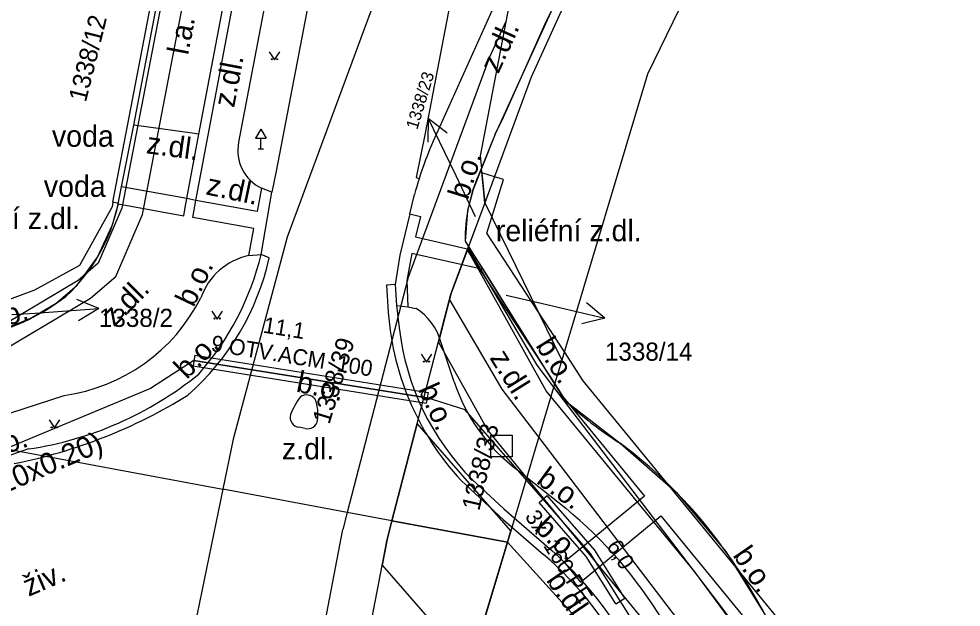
# Model space of a CAD drawing. Extents: x -601602 to -600882, y -1162594 to -1161950.
# Drawn here: x -601319.58 to -601275.41, y -1162307.5 to -1162279.93 of the extents above; entities that cross this region are included whole.
import ezdxf

# ---------------------------------------------------------------- set-up
doc = ezdxf.new("R2010")
doc.units = 0
for name, color, linetype in [('KN_Hranice parcel', 7, 'Continuous'), ('KN_Parcelní čísla', 7, 'Continuous'), ('KN_Pop  PČ popisy', 7, 'Continuous'), ('KN_Vnitřní kresba', 7, 'Continuous'), ('KN_Věcná břemena k části', 7, 'Continuous'), ('VRSTVA 1', 7, 'Continuous'), ('Vrstva 13', 7, 'Continuous'), ('Vrstva 14', 7, 'Continuous'), ('Vrstva 16', 7, 'Continuous'), ('VRSTVA 3', 7, 'Continuous'), ('VRSTVA 5', 7, 'Continuous'), ('Vrstva 6', 7, 'Continuous'), ('Vrstva 8', 7, 'Continuous')]:
    doc.layers.add(name, color=color, linetype=linetype)

# ---------------------------------------------------------------- blocks, each defined once
blk = doc.blocks.new('1029_42')
at = {"layer": 'KN_Pop  PČ popisy'}
for p, q in [((0, 0), (2.924, -0.675)), ((2.924, -0.675), (2.061, 0.038)), ((2.924, -0.675), (1.836, -0.938))]:
    blk.add_line(p, q, dxfattribs=at)
blk = doc.blocks.new('1029_47')
at = {"layer": 'KN_Pop  PČ popisy'}
for p, q in [((-1.316, 2.697), (-1.327, 1.578)), ((0, 0), (-1.316, 2.697)), ((-1.316, 2.697), (-0.426, 2.017))]:
    blk.add_line(p, q, dxfattribs=at)
blk = doc.blocks.new('1029_84')
at = {"layer": 'KN_Pop  PČ popisy'}
for p, q in [((2.994, 0.209), (1.96, 0.639)), ((0, 0), (2.994, 0.209)), ((2.994, 0.209), (2.03, -0.36))]:
    blk.add_line(p, q, dxfattribs=at)
blk = doc.blocks.new('CabR_3')
at = {"layer": 'Vrstva 14'}
blk.add_lwpolyline([(-1, 1), (1, 1), (1, -1), (-1, -1)], close=True, dxfattribs=at)

msp = doc.modelspace()

# ---------------------------------------------------------------- linework, layer by layer
at = {"layer": 'KN_Hranice parcel'}
for p, q in [((-601315.17, -1162288.53), (-601309.39, -1162258.31)), ((-601297.74, -1162288.55), (-601297.9, -1162286.95)), ((-601297.74, -1162288.55), (-601298.5, -1162290.6)), ((-601297.74, -1162288.55), (-601294.13, -1162295.93)), ((-601298.5, -1162290.6), (-601294.47, -1162297.06)), ((-601294.13, -1162295.93), (-601294.47, -1162297.06)), ((-601294.47, -1162297.06), (-601296.68, -1162304.46)), ((-601325.97, -1162299.01), (-601310.02, -1162301.98)), ((-601309.53, -1162299.63), (-601310.02, -1162301.98)), ((-601310.02, -1162301.98), (-601311.33, -1162308.34)), ((-601296.68, -1162304.46), (-601302.09, -1162303.45))]:
    msp.add_line(p, q, dxfattribs=at)
for points in [[(-601292.2, -1162256.23), (-601296.93, -1162266.11), (-601300.03, -1162272.63), (-601303.08, -1162279.58), (-601307.01, -1162290.16), (-601309.53, -1162299.63)], [(-601292.2, -1162256.23), (-601296.76, -1162280.08), (-601297.96, -1162286.36), (-601297.9, -1162286.95)], [(-601290.15, -1162259.19), (-601292, -1162269.8), (-601293.2, -1162275.74), (-601294.16, -1162278.55), (-601297.26, -1162285.34), (-601297.9, -1162286.95)], [(-601284.78, -1162260.22), (-601289.61, -1162269.86), (-601292.03, -1162274.89), (-601295.56, -1162282.66), (-601297.74, -1162288.55)], [(-601279.73, -1162261.19), (-601290.12, -1162282.53), (-601294.13, -1162295.93)], [(-601297.9, -1162286.95), (-601298.29, -1162287.93), (-601298.55, -1162288.92), (-601298.66, -1162290.35), (-601298.5, -1162290.6)], [(-601325.16, -1162296.29), (-601323.67, -1162295.55), (-601322.13, -1162294.94), (-601320.77, -1162294.65), (-601319.05, -1162293.97), (-601317.83, -1162293.26), (-601316.85, -1162292.41), (-601315.89, -1162291.1), (-601315.19, -1162289.58), (-601314.91, -1162288.59), (-601315.17, -1162288.53)], [(-601315.17, -1162288.53), (-601315.21, -1162288.75), (-601316.74, -1162291.49), (-601318.85, -1162292.65), (-601324.73, -1162294.84)], [(-601302.09, -1162303.45), (-601299.33, -1162292.84), (-601298.5, -1162290.6)], [(-601294.47, -1162297.06), (-601294, -1162297.81), (-601291.4, -1162299.81), (-601288.77, -1162302.11), (-601286.44, -1162304.9), (-601284.62, -1162307.84), (-601283.14, -1162310.6), (-601281.69, -1162312.15), (-601279.73, -1162313.35), (-601233.13, -1162322.35), (-601185.37, -1162331.34)], [(-601302.09, -1162303.45), (-601304.19, -1162303.06), (-601310.02, -1162301.98)], [(-600919.037, -1162396.971), (-600927.7, -1162395.33), (-600949.5, -1162391.18), (-600985.92, -1162384.31), (-601061.31, -1162370.08), (-601128.39, -1162357.28), (-601192.59, -1162345.07), (-601263.97, -1162331.56), (-601288.82, -1162326.8), (-601298.71, -1162324.89), (-601298.28, -1162322.82), (-601301.35, -1162321.33), (-601304.05, -1162318.46), (-601304.21, -1162314.16), (-601302.32, -1162304.33), (-601302.09, -1162303.45)], [(-601296.68, -1162304.46), (-601298.54, -1162310.66), (-601297.99, -1162318.35), (-601285.76, -1162320.53), (-601213.14, -1162334.77)]]:
    msp.add_lwpolyline(points, dxfattribs=at)
at = {"layer": 'KN_Pop  PČ popisy'}
for p, q in [((-601298.17, -1162289.21), (-601299.08, -1162287.29)), ((-601296.73, -1162292.88), (-601295.03, -1162293.28)), ((-601319.91, -1162293.79), (-601318.82, -1162293.72))]:
    msp.add_line(p, q, dxfattribs=at)
at = {"layer": 'KN_Vnitřní kresba'}
for p, q in [((-601297.5, -1162281.71), (-601296.76, -1162280.08)), ((-601301.34, -1162292.11), (-601297.5, -1162281.71)), ((-601301.34, -1162292.11), (-601304.19, -1162303.06)), ((-601304.19, -1162303.06), (-601304.4, -1162303.86)), ((-601306.31, -1162313.97), (-601304.4, -1162303.86))]:
    msp.add_line(p, q, dxfattribs=at)
at = {"layer": 'KN_Věcná břemena k části'}
for points in [[(-601325.9, -1162298.77), (-601316.22, -1162293.02), (-601315.03, -1162292), (-601313.79, -1162289.1), (-601307.84, -1162258.18), (-601307.37, -1162255.4), (-601308.71, -1162257.33), (-601308.82, -1162258.01), (-601314.76, -1162288.81), (-601315.86, -1162291.39), (-601316.8, -1162292.2), (-601325.48, -1162297.36)], [(-601279.01, -1162321.85), (-601278.66, -1162319.78), (-601279.07, -1162317.81), (-601287.9, -1162305.85), (-601294.64, -1162297.63), (-601294.86, -1162297.36), (-601298.55, -1162290.75), (-601299.33, -1162292.84), (-601299.91, -1162295.08), (-601297.6, -1162299.22), (-601295.78, -1162301.44), (-601290.5, -1162307.87), (-601282.21, -1162319.13), (-601282.2, -1162319.78), (-601282.43, -1162321.18)], [(-601296.68, -1162304.46), (-601296.52, -1162303.93), (-601300.91, -1162298.89), (-601302.09, -1162303.45)], [(-601298.42, -1162310.27), (-601296.68, -1162304.46), (-601302.09, -1162303.45), (-601302.32, -1162304.33), (-601302.55, -1162305.53)], [(-601285.76, -1162320.53), (-601281.32, -1162321.4), (-601296.68, -1162304.46), (-601298.42, -1162310.27), (-601290.19, -1162319.74)]]:
    msp.add_lwpolyline(points, close=True, dxfattribs=at)
for points in [[(-601276.28, -1162317.43), (-601288.94, -1162302.01), (-601293.13, -1162296.89), (-601294.01, -1162295.54), (-601295.26, -1162293.63), (-601297.64, -1162289.97), (-601297.41, -1162289.23), (-601296.86, -1162287.47), (-601297.29, -1162287.33), (-601297.88, -1162287.15), (-601297.74, -1162288.55), (-601298.56, -1162290.77), (-601294.46, -1162297.04), (-601294.09, -1162297.61), (-601290.25, -1162302.3), (-601294.02, -1162305.4), (-601293.25, -1162306.33), (-601289.48, -1162303.23), (-601277.6, -1162317.73)], [(-601209.38, -1162327.74), (-601275.12, -1162315.35), (-601278.09, -1162316.28), (-601278.9, -1162317.85), (-601279.27, -1162317.66), (-601286.61, -1162307.54), (-601294.51, -1162297.19), (-601295.28, -1162296.17), (-601298.52, -1162290.66), (-601299.33, -1162292.84), (-601299.4, -1162293.1), (-601296.94, -1162297.29), (-601295.21, -1162299.55), (-601288.21, -1162308.74), (-601280.59, -1162319.26), (-601279.52, -1162319.76), (-601279.87, -1162321.69), (-601281.06, -1162328.29), (-601279.1, -1162328.66), (-601277.9, -1162322.07), (-601277.4, -1162319.32), (-601276.69, -1162317.94), (-601275, -1162317.41), (-601209.74, -1162329.7)]]:
    msp.add_lwpolyline(points, dxfattribs=at)
at = {"layer": 'VRSTVA 1'}
for points in [[(-601297.08, -1162300.063), (-601298.66, -1162298.25), (-601300.44, -1162297.69), (-601311.37, -1162295.94), (-601313.41, -1162297.25), (-601324.41, -1162301.83), (-601331.31, -1162306.58)], [(-601275.371, -1162318.188), (-601275.39, -1162318.185), (-601276.28, -1162318.06), (-601281.81, -1162316.83), (-601284.51, -1162316.21), (-601287.04, -1162314.12), (-601288.27, -1162312.16), (-601291.39, -1162307.21), (-601292.79, -1162304.98), (-601295.01, -1162302.44), (-601297.08, -1162300.063)]]:
    msp.add_lwpolyline(points, dxfattribs=at)
at = {"layer": 'Vrstva 13'}
for p, q in [((-601314.19, -1162284.92), (-601311.3, -1162269.78)), ((-601304.24, -1162269.94), (-601307.52, -1162287.07)), ((-601297.53, -1162269.63), (-601300.54, -1162285.29)), ((-601311.29, -1162288.44), (-601308.13, -1162271.77)), ((-601311.14, -1162285.34), (-601308.52, -1162271.6)), ((-601307.94, -1162278.68), (-601309.28, -1162285.72)), ((-601297.19, -1162279.07), (-601300.01, -1162285.33)), ((-601296.87, -1162284.54), (-601294.84, -1162280.03)), ((-601297.26, -1162285.34), (-601296.87, -1162284.54)), ((-601314.77, -1162287.81), (-601314.19, -1162284.92)), ((-601311.57, -1162285.28), (-601314.19, -1162284.92)), ((-601311.71, -1162288.36), (-601311.14, -1162285.34)), ((-601311.14, -1162285.34), (-601311.57, -1162285.28)), ((-601300.54, -1162285.29), (-601300.95, -1162287.37)), ((-601297.26, -1162285.34), (-601298.05, -1162287.3)), ((-601307.52, -1162287.07), (-601307.72, -1162288.06)), ((-601300.95, -1162287.37), (-601300.81, -1162287.41)), ((-601314.92, -1162288.6), (-601314.77, -1162287.81)), ((-601311.71, -1162288.36), (-601314.77, -1162287.81)), ((-601308.2, -1162287.87), (-601308.41, -1162288.96)), ((-601308.22, -1162290.97), (-601307.72, -1162288.06)), ((-601307.72, -1162288.06), (-601308.2, -1162287.87)), ((-601311.78, -1162288.78), (-601311.71, -1162288.36)), ((-601311.29, -1162288.44), (-601311.71, -1162288.36)), ((-601311.42, -1162289.24), (-601311.29, -1162288.44)), ((-601308.41, -1162288.96), (-601311.29, -1162288.44)), ((-601301.26, -1162289.07), (-601301.03, -1162288.16)), ((-601314.92, -1162288.6), (-601311.844, -1162289.163)), ((-601311.844, -1162289.163), (-601311.78, -1162288.78)), ((-601308.56, -1162289.76), (-601311.42, -1162289.24)), ((-601301.26, -1162289.07), (-601301.72, -1162291.01)), ((-601301.26, -1162289.07), (-601300.75, -1162289.2)), ((-601300.75, -1162289.2), (-601300.99, -1162290.15)), ((-601308.8, -1162291.03), (-601308.56, -1162289.76)), ((-601300.99, -1162290.15), (-601298.42, -1162290.74)), ((-601298.66, -1162290.35), (-601298.42, -1162290.74)), ((-601298.42, -1162290.74), (-601297.82, -1162291.68)), ((-601308.8, -1162291.03), (-601308.22, -1162290.97)), ((-601307.84, -1162291.13), (-601308.22, -1162290.97)), ((-601301.72, -1162291.01), (-601301.94, -1162292.39)), ((-601301.16, -1162290.93), (-601301.39, -1162292.19)), ((-601297.82, -1162291.68), (-601301.16, -1162290.93)), ((-601297.82, -1162291.68), (-601294, -1162297.81)), ((-601301.94, -1162292.39), (-601302.35, -1162292.42)), ((-601302.35, -1162292.42), (-601302.28, -1162293.41)), ((-601301.94, -1162292.39), (-601301.88, -1162293.36)), ((-601301.39, -1162292.19), (-601301.34, -1162293.43)), ((-601301.88, -1162293.36), (-601301.34, -1162293.43)), ((-601301.88, -1162293.36), (-601301.75, -1162294.42)), ((-601301.34, -1162293.43), (-601300.96, -1162293.5)), ((-601299.17, -1162296.94), (-601299.8, -1162295.07)), ((-601321.6, -1162298.92), (-601317.46, -1162297.58)), ((-601306.16, -1162299.13), (-601306.46, -1162299.07)), ((-601296.19, -1162301.09), (-601293.94, -1162302.87)), ((-601298.85, -1162301.57), (-601296.86, -1162303.41)), ((-601298.32, -1162301.54), (-601296.84, -1162302.9)), ((-601296.84, -1162302.9), (-601294.59, -1162304.85)), ((-601296.86, -1162303.41), (-601294.99, -1162305.03))]:
    msp.add_line(p, q, dxfattribs=at)
for centre, radius, start, end in [((-601315.797, -1162269.57), 23.422, 333.4761, 350.4407), ((-601283.27, -1162292.962), 18.398, 155.4903, 164.869), ((-601307.382, -1162286.113), 1.938, 168.3057, 245.0374), ((-601291.28, -1162290.24), 7.381, 156.5262, 180.8539), ((-601322.869, -1162286.962), 8.116, 312.556, 348.3531), ((-601319.677, -1162288.461), 12.134, 311.354, 347.2959), ((-601321.071, -1162287.828), 13.23, 318.5833, 346.2622), ((-601308.194, -1162293.987), 3.018, 101.5778, 161.1178), ((-601323.588, -1162284.902), 10.156, 277.9669, 307.6791), ((-601318.614, -1162289.181), 8.478, 277.8236, 333.1502), ((-601289.301, -1162292.755), 12.996, 182.8886, 222.7096), ((-601302.424, -1162295.795), 2.723, 15.4524, 57.4656), ((-601289.789, -1162293.044), 12.04, 186.5618, 224.8823), ((-601321.538, -1162283.789), 16.478, 278.403, 309.0816), ((-601291.135, -1162294.315), 8.453, 198.0912, 233.271), ((-601324.502, -1162276.856), 24.372, 281.1238, 301.7978), ((-601302.699, -1162300.251), 4.513, 144.6503, 156.8936), ((-601306.097, -1162298.055), 0.502, 35.9283, 124.34), ((-601307.535, -1162298.463), 1.975, 351.945, 20.8637), ((-601282.227, -1162285.195), 17.256, 226.9773, 237.8855), ((-601306.388, -1162298.598), 0.477, 165.6463, 261.2845), ((-601306.048, -1162298.67), 0.474, 256.3603, 351.4746), ((-601304.926, -1162317.935), 22.615, 35.5682, 53.2673), ((-601312.679, -1162320.585), 21.486, 107.4716, 135.2188), ((-601306.991, -1162318.724), 20.534, 31.0574, 50.5387), ((-601306.894, -1162318.54), 18.407, 26.281, 48.0522), ((-601306.8, -1162319.678), 25.156, 24.9417, 36.3157), ((-601305.647, -1162317.479), 16.387, 26.4088, 49.4333)]:
    msp.add_arc(centre, radius, start, end, dxfattribs=at)
at = {"layer": 'VRSTVA 3'}
for points in [[(-601307.849, -1162281.477), (-601307.599, -1162281.852), (-601307.349, -1162281.477)], [(-601310.535, -1162293.627), (-601310.285, -1162294.002), (-601310.035, -1162293.627)], [(-601300.72, -1162295.645), (-601300.47, -1162296.02), (-601300.22, -1162295.645)], [(-601318.166, -1162298.731), (-601317.916, -1162299.106), (-601317.666, -1162298.731)]]:
    msp.add_lwpolyline(points, dxfattribs=at)
for centre in [(-601307.724, -1162281.827), (-601307.474, -1162281.827), (-601310.41, -1162293.977), (-601310.16, -1162293.977), (-601300.595, -1162295.995), (-601300.345, -1162295.995), (-601318.041, -1162299.081), (-601317.791, -1162299.081)]:
    msp.add_circle(centre, 0.025, dxfattribs=at)
at = {"layer": 'VRSTVA 5'}
for p, q in [((-601311.33, -1162295.693), (-601311.41, -1162296.187)), ((-601311.37, -1162295.94), (-601300.44, -1162297.69)), ((-601311.33, -1162295.693), (-601300.4, -1162297.443)), ((-601311.41, -1162296.187), (-601300.48, -1162297.937)), ((-601300.4, -1162297.443), (-601300.48, -1162297.937)), ((-601295.198, -1162302.605), (-601294.822, -1162302.275)), ((-601291.602, -1162307.343), (-601291.178, -1162307.077))]:
    msp.add_line(p, q, dxfattribs=at)
for points in [[(-601291.178, -1162307.077), (-601292.589, -1162304.83), (-601294.822, -1162302.275)], [(-601291.602, -1162307.343), (-601292.991, -1162305.13), (-601295.198, -1162302.605)], [(-601291.39, -1162307.21), (-601292.79, -1162304.98), (-601295.01, -1162302.44)]]:
    msp.add_lwpolyline(points, dxfattribs=at)
at = {"layer": 'Vrstva 8'}
for p, q in [((-601308.24, -1162285.097), (-601308.49, -1162285.53)), ((-601308.24, -1162285.097), (-601307.99, -1162285.53)), ((-601308.49, -1162285.53), (-601307.99, -1162285.53)), ((-601308.24, -1162286.03), (-601308.24, -1162285.53)), ((-601308.365, -1162286.03), (-601308.115, -1162286.03))]:
    msp.add_line(p, q, dxfattribs=at)

# ---------------------------------------------------------------- block references
at = {"layer": 'KN_Pop  PČ popisy'}
for name, p in [('1029_47', (-601299.08, -1162287.29)), ('1029_84', (-601318.82, -1162293.72)), ('1029_42', (-601295.03, -1162293.28))]:
    msp.add_blockref(name, p, dxfattribs=at)
at = {"layer": 'Vrstva 14', "xscale": 0.5, "yscale": 0.5}
msp.add_blockref('CabR_3', (-601296.95, -1162299.95), dxfattribs=at)

# ---------------------------------------------------------------- texts
at = {"layer": 'KN_Parcelní čísla'}
for s, height, rotation, p in [('1338/12', 0.85, 76, (-601316.438, -1162283.873)), ('1338/23', 0.5695, 73, (-601300.905, -1162285.155)), ('1338/39', 0.85, 73, (-601305.027, -1162298.968)), ('1338/33', 0.85, 77, (-601298.001, -1162303.021))]:
    msp.add_text(s, height=height, rotation=rotation, dxfattribs=at).set_placement(p)
for s, p in [('1338/2', (-601315.83, -1162294.37)), ('1338/14', (-601292.11, -1162295.953))]:
    msp.add_text(s, height=0.85, dxfattribs=at).set_placement(p)
at = {"layer": 'Vrstva 16'}
for s, rotation, p in [('l.a.', 79.1576, (-601311.646, -1162281.663)), ('z.dl.', 65.5807, (-601297.106, -1162282.547)), ('z.dl.', 79.2232, (-601309.492, -1162284.126)), ('z.dl.', 352.1763, (-601313.641, -1162286.228)), ('b.o.', 72.5701, (-601298.53, -1162288.452)), ('z.dl.', 348.1386, (-601310.854, -1162288.155)), ('b.o.', 64.5747, (-601311.389, -1162293.486)), ('z.dl.', 44.8768, (-601315.12, -1162294.392)), ('b.o.', 16.719, (-601321.185, -1162294.647)), ('b.o.', 301.9122, (-601295.385, -1162295.238)), ('b.o.', 44.8768, (-601311.711, -1162296.859)), ('z.dl.', 301.9284, (-601297.537, -1162295.817)), ('b.o.', 348.0588, (-601306.622, -1162297.392)), ('b.o.', 293.9458, (-601300.879, -1162297.281)), ('b.dl.(0.10x0.20)', 23.3792, (-601324.074, -1162303.841)), ('b.o.', 19.5747, (-601321.175, -1162300.696)), ('z.dl.', 0.0968, (-601307.247, -1162300.58)), ('b.o.', 323.7693, (-601295.37, -1162301.661)), ('b.o.', 316.5045, (-601295.459, -1162303.855)), ('b.o.', 304.3543, (-601286.143, -1162305.071)), ('živ.', 23.3792, (-601319.121, -1162307.02)), ('b.dl.(0.10x0.20)', 304.3543, (-601294.891, -1162306.237))]:
    msp.add_text(s, height=1, rotation=rotation, dxfattribs=at).set_placement(p)
for s, p in [('voda', (-601318.028, -1162285.927)), ('voda', (-601318.41, -1162288.275)), ('reliéfní z.dl.', (-601323.547, -1162289.786)), ('reliéfní z.dl.', (-601297.223, -1162290.356))]:
    msp.add_text(s, height=1, dxfattribs=at).set_placement(p)
at = {"layer": 'Vrstva 6'}
for s, rotation, p in [('11,1', 350.9036, (-601308.164, -1162294.635)), ('9 OTV.ACM  100', 350.9036, (-601310.606, -1162295.493)), ('3x  160 PE', 302.1764, (-601295.882, -1162303.247)), ('6,0', 302.1764, (-601292.059, -1162304.636))]:
    msp.add_text(s, height=0.75, rotation=rotation, dxfattribs=at).set_placement(p)

doc.saveas('drawing.dxf')
